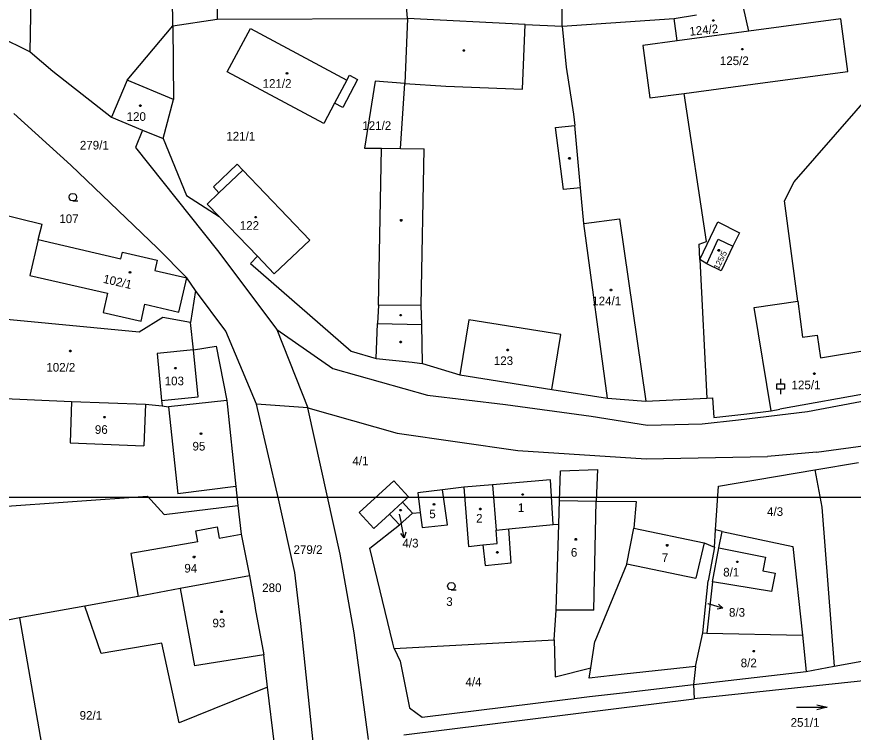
# Model space of a CAD drawing. Extents: x -812394 to -807601, y -1013097 to -1009266.
# Drawn here: x -809776.7 to -809612.2, y -1010813 to -1010672.5 of the extents above; entities that cross this region are included whole.
import ezdxf

# ---------------------------------------------------------------- set-up
doc = ezdxf.new("R2010")
doc.units = 0
for name, color, linetype in [('Default', 7, 'Continuous'), ('KN_HRANICE', 7, 'Continuous'), ('KN_KULTURY', 7, 'Continuous'), ('KN_PARCELY', 7, 'Continuous'), ('KN_SLUCKY', 7, 'Continuous'), ('LEGENDA', 7, 'Continuous')]:
    doc.layers.add(name, color=color, linetype=linetype)

# ---------------------------------------------------------------- blocks, each defined once
blk = doc.blocks.new('10292')
at = {"layer": 'Default'}
blk.add_line((0, 3), (0, 0), dxfattribs=at)
blk.add_lwpolyline([(-0.5, 2), (0, 3), (0.5, 2)], dxfattribs=at)
blk = doc.blocks.new('304')
at = {"layer": 'Default'}
blk.add_lwpolyline([(0, 0), (-0.38, 0.1), (-0.65, 0.37), (-0.75, 0.74), (-0.65, 1.11), (-0.38, 1.38), (-0.01, 1.48), (0.36, 1.38), (0.63, 1.11), (0.73, 0.73), (0.63, 0.35), (0.36, 0.08), (-0.02, -0.02), (0.98, -0.02)], dxfattribs=at)
blk = doc.blocks.new('NAHRADNI_SYMBOL')
at = {"layer": 'Default'}
blk.add_lwpolyline([(0.09, 0.15), (0.18, 0), (0.09, -0.15), (-0.09, -0.15), (-0.18, 0), (-0.09, 0.15), (0.09, 0.15)], dxfattribs=at)
blk = doc.blocks.new('802')
at = {"layer": 'Default'}
blk.add_line((-3, 0), (3, 0), dxfattribs=at)
blk.add_lwpolyline([(1, 0.5), (3, 0), (1, -0.5)], dxfattribs=at)
blk = doc.blocks.new('318')
at = {"layer": 'Default'}
blk.add_line((0, 2), (0, 3), dxfattribs=at)
blk.add_lwpolyline([(0, 0), (0, 1), (-0.75, 1), (-0.75, 2), (0, 2), (0.75, 2), (0.75, 1), (0, 1)], dxfattribs=at)
blk = doc.blocks.new('402')
at = {"layer": 'Default'}
blk.add_lwpolyline([(0.09, 0.15), (0.18, 0), (0.09, -0.15), (-0.09, -0.15), (-0.18, 0), (-0.09, 0.15), (0.09, 0.15)], dxfattribs=at)

msp = doc.modelspace()

# ---------------------------------------------------------------- linework, layer by layer
at = {"layer": 'KN_HRANICE'}
for p, q in [((-809669.42, -1010674.32), (-809670.02, -1010597.72)), ((-809738.29, -1010601.65), (-809737.29, -1010672.93)), ((-809745.99, -1010674.27), (-809746.74, -1010602.54)), ((-809699.85, -1010672.81), (-809703, -1010635.36)), ((-809774.04, -1010679.33), (-809773.49, -1010652.65)), ((-809632.78, -1010675.32), (-809633.83, -1010670.62)), ((-809737.29, -1010672.93), (-809699.85, -1010672.81)), ((-809699.85, -1010672.81), (-809700.37, -1010685.55)), ((-809676.74, -1010673.97), (-809699.85, -1010672.81)), ((-809669.42, -1010674.32), (-809647.44, -1010672.82)), ((-809647.44, -1010672.82), (-809643.04, -1010672.11)), ((-809646.86, -1010677.2), (-809647.44, -1010672.82)), ((-809614.65, -1010672.88), (-809632.78, -1010675.32)), ((-809613.27, -1010683.22), (-809614.65, -1010672.88)), ((-809784.4, -1010674.33), (-809774.04, -1010679.33)), ((-809754.98, -1010684.91), (-809745.99, -1010674.27)), ((-809745.99, -1010674.27), (-809737.29, -1010672.93)), ((-809745.99, -1010674.27), (-809745.83, -1010688.74)), ((-809676.74, -1010673.97), (-809669.42, -1010674.32)), ((-809669.42, -1010674.32), (-809668.69, -1010682.36)), ((-809735.29, -1010683.27), (-809730.75, -1010674.77)), ((-809730.75, -1010674.77), (-809711.79, -1010684.94)), ((-809632.78, -1010675.32), (-809646.86, -1010677.2)), ((-809646.86, -1010677.2), (-809653.59, -1010678.08)), ((-809774.04, -1010679.33), (-809769.56, -1010683.18)), ((-809653.59, -1010678.08), (-809652.21, -1010688.42)), ((-809668.69, -1010682.36), (-809667.2, -1010691.63)), ((-809769.56, -1010683.18), (-809758.03, -1010692.2)), ((-809716.29, -1010693.43), (-809735.29, -1010683.27)), ((-809711.79, -1010684.94), (-809711.27, -1010683.97)), ((-809711.27, -1010683.97), (-809709.68, -1010684.81)), ((-809630.51, -1010685.51), (-809613.27, -1010683.22)), ((-809754.98, -1010684.91), (-809758.03, -1010692.2)), ((-809709.68, -1010684.81), (-809712.59, -1010690.29)), ((-809706.24, -1010685.14), (-809708.32, -1010698.31)), ((-809700.37, -1010685.55), (-809706.24, -1010685.14)), ((-809701.22, -1010698.32), (-809700.37, -1010685.55)), ((-809645.48, -1010687.51), (-809630.51, -1010685.51)), ((-809652.21, -1010688.42), (-809645.48, -1010687.51)), ((-809641.11, -1010716.62), (-809645.48, -1010687.51)), ((-809747.86, -1010696.38), (-809745.83, -1010688.74)), ((-809714.18, -1010689.45), (-809716.29, -1010693.43)), ((-809712.59, -1010690.29), (-809714.18, -1010689.45)), ((-809777.22, -1010691.48), (-809766.01, -1010701.62)), ((-809758.03, -1010692.2), (-809751.95, -1010694.73)), ((-809667.2, -1010691.63), (-809666.99, -1010693.85)), ((-809665.84, -1010706.07), (-809666.99, -1010693.85)), ((-809751.95, -1010694.73), (-809753.31, -1010698.15)), ((-809751.95, -1010694.73), (-809747.86, -1010696.38)), ((-809747.86, -1010696.38), (-809743.3, -1010707.57)), ((-809753.31, -1010698.15), (-809737.22, -1010718.42)), ((-809708.32, -1010698.31), (-809704.94, -1010698.29)), ((-809705.58, -1010729.13), (-809704.94, -1010698.29)), ((-809704.94, -1010698.29), (-809701.22, -1010698.32)), ((-809766.01, -1010701.62), (-809749.02, -1010717.93)), ((-809738.02, -1010705.9), (-809733.32, -1010701.42)), ((-809733.32, -1010701.42), (-809732.21, -1010702.59)), ((-809732.21, -1010702.59), (-809719.07, -1010716.39)), ((-809739.24, -1010709.28), (-809736.91, -1010707.06)), ((-809736.91, -1010707.06), (-809738.02, -1010705.9)), ((-809665.18, -1010713.11), (-809665.84, -1010706.07)), ((-809743.3, -1010707.57), (-809736.88, -1010711.74)), ((-809736.88, -1010711.74), (-809739.24, -1010709.28)), ((-809781.21, -1010710.87), (-809771.66, -1010713.22)), ((-809729.37, -1010719.53), (-809736.88, -1010711.74)), ((-809772.47, -1010716.21), (-809771.66, -1010713.22)), ((-809660.52, -1010747.43), (-809665.18, -1010713.11)), ((-809642.41, -1010720.19), (-809638.87, -1010712.74)), ((-809638.87, -1010712.74), (-809634.6, -1010714.95)), ((-809634.6, -1010714.95), (-809635.89, -1010717.53)), ((-809772.47, -1010716.21), (-809756.21, -1010720.01)), ((-809719.07, -1010716.39), (-809726.06, -1010722.97)), ((-809642.51, -1010717.16), (-809641.11, -1010716.62)), ((-809642.41, -1010720.19), (-809642.51, -1010717.16)), ((-809756.21, -1010720.01), (-809755.91, -1010718.7)), ((-809755.91, -1010718.7), (-809749.04, -1010720.31)), ((-809749.02, -1010717.93), (-809743.23, -1010723.77)), ((-809737.22, -1010718.42), (-809725.56, -1010733.93)), ((-809635.89, -1010717.53), (-809638.17, -1010722.36)), ((-809749.04, -1010720.31), (-809749.51, -1010722.3)), ((-809729.37, -1010719.53), (-809730.7, -1010720.97)), ((-809726.06, -1010722.97), (-809729.37, -1010719.53)), ((-809642.41, -1010720.19), (-809641.01, -1010747.39)), ((-809641.03, -1010721), (-809642.41, -1010720.19)), ((-809730.7, -1010720.97), (-809710.9, -1010738.19)), ((-809638.17, -1010722.36), (-809641.03, -1010721)), ((-809749.51, -1010722.3), (-809743.23, -1010723.77)), ((-809741.5, -1010726.25), (-809743.23, -1010723.77)), ((-809741.5, -1010726.25), (-809742.53, -1010732.53)), ((-809735.54, -1010734.22), (-809741.5, -1010726.25)), ((-809623.13, -1010728.35), (-809622.2, -1010735.4)), ((-809705.58, -1010729.13), (-809705.74, -1010732.73)), ((-809752.63, -1010734.46), (-809779.32, -1010731.85)), ((-809747.95, -1010731.58), (-809752.63, -1010734.46)), ((-809742.53, -1010732.53), (-809747.95, -1010731.58)), ((-809741.93, -1010737.9), (-809742.53, -1010732.53)), ((-809706.04, -1010739.63), (-809705.74, -1010732.73)), ((-809729.55, -1010748.61), (-809735.54, -1010734.22)), ((-809725.56, -1010733.93), (-809719.43, -1010749.27)), ((-809725.56, -1010733.93), (-809714.56, -1010741.6)), ((-809741.93, -1010737.9), (-809749.09, -1010738.63)), ((-809749.09, -1010738.63), (-809748.19, -1010747.84)), ((-809741.93, -1010737.9), (-809737.44, -1010737.2)), ((-809737.44, -1010737.2), (-809735.38, -1010747.89)), ((-809710.9, -1010738.19), (-809706.04, -1010739.63)), ((-809618.66, -1010739.51), (-809608.17, -1010737.7)), ((-809706.04, -1010739.63), (-809698.97, -1010740.34)), ((-809714.56, -1010741.6), (-809695.94, -1010746.84)), ((-809698.97, -1010740.34), (-809697.48, -1010740.51)), ((-809697.48, -1010740.51), (-809696.89, -1010740.57)), ((-809696.89, -1010740.57), (-809689.54, -1010742.83)), ((-809689.54, -1010742.83), (-809671.5, -1010745.72)), ((-809695.94, -1010746.84), (-809680.59, -1010748.64)), ((-809671.5, -1010745.72), (-809660.52, -1010747.43)), ((-809606.66, -1010745.99), (-809626.64, -1010749.55)), ((-809621.25, -1010750.05), (-809601.6, -1010746.29)), ((-809785.91, -1010747.13), (-809765.89, -1010748.07)), ((-809765.89, -1010748.07), (-809766.17, -1010756.16)), ((-809765.89, -1010748.07), (-809751.37, -1010748.58)), ((-809748.19, -1010747.84), (-809748.08, -1010748.94)), ((-809735.38, -1010747.89), (-809746.82, -1010749.08)), ((-809735.38, -1010747.89), (-809733.57, -1010764.79)), ((-809660.52, -1010747.43), (-809652.99, -1010747.99)), ((-809652.99, -1010747.99), (-809641.01, -1010747.39)), ((-809641.01, -1010747.39), (-809639.91, -1010747.34)), ((-809639.91, -1010747.34), (-809639.63, -1010751.19)), ((-809751.37, -1010748.58), (-809751.66, -1010756.76)), ((-809751.37, -1010748.58), (-809748.08, -1010748.94)), ((-809748.08, -1010748.94), (-809746.82, -1010749.08)), ((-809719.43, -1010749.27), (-809729.55, -1010748.61)), ((-809725.23, -1010767.15), (-809729.55, -1010748.61)), ((-809713.08, -1010778.05), (-809719.43, -1010749.27)), ((-809719.43, -1010749.27), (-809701.9, -1010754.25)), ((-809680.59, -1010748.64), (-809663.74, -1010750.97)), ((-809634.81, -1010751.63), (-809621.25, -1010750.05)), ((-809633.16, -1010750.47), (-809628.36, -1010749.86)), ((-809628.36, -1010749.86), (-809626.64, -1010749.55)), ((-809663.74, -1010750.97), (-809652.69, -1010752.68)), ((-809641.93, -1010752.44), (-809634.81, -1010751.63)), ((-809639.63, -1010751.19), (-809633.16, -1010750.47)), ((-809652.69, -1010752.68), (-809641.93, -1010752.44)), ((-809701.9, -1010754.25), (-809678.17, -1010757.69)), ((-809766.17, -1010756.16), (-809751.66, -1010756.76)), ((-809619.48, -1010758), (-809604.22, -1010755.92)), ((-809678.17, -1010757.69), (-809652.96, -1010759.33)), ((-809619.48, -1010758), (-809629.11, -1010758.87)), ((-809652.96, -1010759.33), (-809629.11, -1010758.87)), ((-809669.98, -1010767.52), (-809669.8, -1010761.66)), ((-809669.8, -1010761.66), (-809662.52, -1010761.44)), ((-809662.52, -1010761.44), (-809662.78, -1010767.62)), ((-809638.74, -1010764.69), (-809619.76, -1010761.5)), ((-809619.76, -1010761.5), (-809611.19, -1010760.06)), ((-809619.76, -1010761.5), (-809618.42, -1010768.8)), ((-809733.57, -1010764.79), (-809733.18, -1010768.47)), ((-809702.57, -1010763.63), (-809709.33, -1010769.84)), ((-809699.69, -1010766.77), (-809702.57, -1010763.63)), ((-809688.81, -1010764.89), (-809692.96, -1010765.39)), ((-809683.14, -1010764.42), (-809688.81, -1010764.89)), ((-809688.81, -1010764.89), (-809687.88, -1010776.52)), ((-809671.72, -1010763.46), (-809683.14, -1010764.42)), ((-809683.14, -1010764.42), (-809682.45, -1010773.34)), ((-809671.19, -1010772.24), (-809671.72, -1010763.46)), ((-809639.3, -1010773.28), (-809638.74, -1010764.69)), ((-809692.96, -1010765.39), (-809697.85, -1010765.98)), ((-809697.85, -1010765.98), (-809697.36, -1010769.88)), ((-809692.01, -1010772.28), (-809692.96, -1010765.39)), ((-809794.5, -1010769.7), (-809750.96, -1010766.66)), ((-809750.96, -1010766.66), (-809747.68, -1010770.25)), ((-809722.03, -1010781.65), (-809725.23, -1010767.15)), ((-809700.87, -1010767.86), (-809699.69, -1010766.77)), ((-809698.9, -1010770), (-809700.87, -1010767.86)), ((-809670.12, -1010772.14), (-809669.98, -1010767.52)), ((-809662.78, -1010767.62), (-809654.89, -1010767.73)), ((-809654.89, -1010767.73), (-809655.37, -1010772.93)), ((-809747.68, -1010770.25), (-809733.18, -1010768.47)), ((-809733.18, -1010768.47), (-809732.57, -1010774.14)), ((-809709.33, -1010769.84), (-809706.45, -1010772.98)), ((-809698.9, -1010770), (-809697.36, -1010769.88)), ((-809697.36, -1010769.88), (-809696.98, -1010772.84)), ((-809618.42, -1010768.8), (-809615.96, -1010800.09)), ((-809706.45, -1010772.98), (-809703.38, -1010770.17)), ((-809703.38, -1010770.17), (-809701.41, -1010772.31)), ((-809701.41, -1010772.31), (-809698.9, -1010770)), ((-809707.23, -1010776.9), (-809701.41, -1010772.31)), ((-809696.98, -1010772.84), (-809692.01, -1010772.28)), ((-809682.45, -1010773.34), (-809679.95, -1010773.09)), ((-809679.95, -1010773.09), (-809671.19, -1010772.24)), ((-809679.45, -1010779.76), (-809679.95, -1010773.09)), ((-809671.19, -1010772.24), (-809670.12, -1010772.14)), ((-809670.64, -1010789.08), (-809670.12, -1010772.14)), ((-809656.71, -1010779.93), (-809655.37, -1010772.93)), ((-809655.37, -1010772.93), (-809641.57, -1010775.83)), ((-809732.57, -1010774.14), (-809730.91, -1010782.33)), ((-809639.52, -1010776.68), (-809639.3, -1010773.28)), ((-809638.02, -1010773.59), (-809639.3, -1010773.28)), ((-809638.65, -1010776.84), (-809638.02, -1010773.59)), ((-809638.02, -1010773.59), (-809624.14, -1010776.53)), ((-809687.88, -1010776.52), (-809685.04, -1010776.24)), ((-809685.04, -1010776.24), (-809684.59, -1010780.3)), ((-809641.57, -1010775.83), (-809639.52, -1010776.68)), ((-809710.32, -1010793.53), (-809713.08, -1010778.05)), ((-809702.75, -1010795.56), (-809707.23, -1010776.9)), ((-809639.52, -1010776.68), (-809640.74, -1010783.28)), ((-809639.93, -1010783.49), (-809638.65, -1010776.84)), ((-809624.14, -1010776.53), (-809622.24, -1010794)), ((-809684.59, -1010780.3), (-809679.45, -1010779.76)), ((-809656.71, -1010779.93), (-809663.05, -1010795.21)), ((-809730.91, -1010782.33), (-809744.52, -1010784.82)), ((-809730.91, -1010782.33), (-809729.89, -1010788.11)), ((-809720.85, -1010791.69), (-809722.03, -1010781.65)), ((-809641.81, -1010793.54), (-809640.74, -1010783.28)), ((-809639.93, -1010783.49), (-809640.99, -1010793.56)), ((-809752.77, -1010786.34), (-809763.26, -1010788.24)), ((-809744.52, -1010784.82), (-809752.77, -1010786.34)), ((-809763.26, -1010788.24), (-809776.12, -1010790.59)), ((-809760.07, -1010797.59), (-809763.26, -1010788.24)), ((-809729.89, -1010788.11), (-809729.78, -1010788.7)), ((-809729.78, -1010788.7), (-809728.11, -1010797.8)), ((-809671, -1010794.86), (-809670.64, -1010789.08)), ((-809776.12, -1010790.59), (-809802.82, -1010795.47)), ((-809776.12, -1010790.59), (-809768.91, -1010832.11)), ((-809718.25, -1010816.21), (-809720.85, -1010791.69)), ((-809707.49, -1010814.44), (-809710.32, -1010793.53)), ((-809643.26, -1010800.13), (-809641.81, -1010793.54)), ((-809641.81, -1010793.54), (-809640.99, -1010793.56)), ((-809640.99, -1010793.56), (-809622.24, -1010794)), ((-809622.24, -1010794), (-809621.47, -1010801.11)), ((-809748.14, -1010795.55), (-809760.07, -1010797.59)), ((-809744.75, -1010811.18), (-809748.14, -1010795.55)), ((-809702.5, -1010796.59), (-809702.75, -1010795.56)), ((-809702.5, -1010796.59), (-809671, -1010794.86)), ((-809671, -1010794.86), (-809670.86, -1010802.13)), ((-809663.83, -1010800.36), (-809663.05, -1010795.21)), ((-809615.96, -1010800.09), (-809588.54, -1010794.9)), ((-809727.35, -1010804.19), (-809728.11, -1010797.8)), ((-809702.5, -1010796.59), (-809701.33, -1010799.05)), ((-809701.33, -1010799.05), (-809699.46, -1010808.24)), ((-809670.86, -1010802.13), (-809663.83, -1010800.36)), ((-809664.14, -1010802.41), (-809663.83, -1010800.36)), ((-809643.26, -1010800.13), (-809657.25, -1010801.66)), ((-809643.26, -1010800.13), (-809643.65, -1010803.69)), ((-809643.65, -1010803.69), (-809621.47, -1010801.11)), ((-809621.47, -1010801.11), (-809615.96, -1010800.09)), ((-809657.25, -1010801.66), (-809664.14, -1010802.41)), ((-809600.38, -1010801.89), (-809643.49, -1010806.47)), ((-809727.35, -1010804.19), (-809744.75, -1010811.18)), ((-809726.02, -1010815.44), (-809727.35, -1010804.19)), ((-809657.57, -1010805.27), (-809643.65, -1010803.69)), ((-809643.65, -1010803.69), (-809643.49, -1010806.47)), ((-809696.99, -1010810.11), (-809664.09, -1010806.01)), ((-809664.09, -1010806.01), (-809657.57, -1010805.27)), ((-809700.6, -1010813.52), (-809643.49, -1010806.47)), ((-809699.46, -1010808.24), (-809696.99, -1010810.11))]:
    msp.add_line(p, q, dxfattribs=at)
for points in [[(-809623.13, -1010728.35), (-809625.78, -1010708.61), (-809623.83, -1010704.87), (-809603.55, -1010681.64)], [(-809622.2, -1010735.4), (-809619.34, -1010735.04), (-809618.66, -1010739.51)]]:
    msp.add_lwpolyline(points, dxfattribs=at)
at = {"layer": 'KN_PARCELY'}
for p, q in [((-809701.47, -1010770.18), (-809701.11, -1010771.9)), ((-809640.83, -1010787.76), (-809640.77, -1010787.78))]:
    msp.add_line(p, q, dxfattribs=at)
at = {"layer": 'KN_SLUCKY'}
for p, q in [((-809677.26, -1010686.71), (-809676.74, -1010673.97)), ((-809745.83, -1010688.74), (-809754.98, -1010684.91)), ((-809711.79, -1010684.94), (-809714.18, -1010689.45)), ((-809700.37, -1010685.55), (-809692.3, -1010686.07)), ((-809692.3, -1010686.07), (-809677.26, -1010686.71)), ((-809670.75, -1010694.2), (-809666.99, -1010693.85)), ((-809669.2, -1010706.39), (-809670.75, -1010694.2)), ((-809701.22, -1010698.32), (-809696.59, -1010698.39)), ((-809697.15, -1010729.18), (-809696.59, -1010698.39)), ((-809736.91, -1010707.06), (-809732.21, -1010702.59)), ((-809665.84, -1010706.07), (-809669.2, -1010706.39)), ((-809665.18, -1010713.11), (-809658.18, -1010712.2)), ((-809658.18, -1010712.2), (-809652.99, -1010747.99)), ((-809772.47, -1010716.21), (-809774.12, -1010723.27)), ((-809641.03, -1010721), (-809638.78, -1010716.15)), ((-809638.78, -1010716.15), (-809635.89, -1010717.53)), ((-809774.12, -1010723.27), (-809758.82, -1010726.77)), ((-809744.81, -1010730.49), (-809743.23, -1010723.77)), ((-809758.82, -1010726.77), (-809759.68, -1010730.55)), ((-809631.7, -1010729.58), (-809623.13, -1010728.35)), ((-809752.23, -1010732.25), (-809751.48, -1010728.96)), ((-809751.48, -1010728.96), (-809744.81, -1010730.49)), ((-809697.15, -1010729.18), (-809705.58, -1010729.13)), ((-809697.06, -1010732.94), (-809697.15, -1010729.18)), ((-809628.36, -1010749.86), (-809631.7, -1010729.58)), ((-809759.68, -1010730.55), (-809752.23, -1010732.25)), ((-809687.81, -1010731.99), (-809689.54, -1010742.83)), ((-809669.72, -1010734.88), (-809687.81, -1010731.99)), ((-809705.74, -1010732.73), (-809697.06, -1010732.94)), ((-809696.89, -1010740.57), (-809697.06, -1010732.94)), ((-809671.5, -1010745.72), (-809669.72, -1010734.88)), ((-809741.03, -1010747.11), (-809741.93, -1010737.9)), ((-809748.19, -1010747.84), (-809741.03, -1010747.11)), ((-809746.82, -1010749.08), (-809744.99, -1010766.19)), ((-809733.57, -1010764.79), (-809744.99, -1010766.19)), ((-809703.38, -1010770.17), (-809700.87, -1010767.86)), ((-809669.98, -1010767.52), (-809662.78, -1010767.62)), ((-809663.25, -1010789.07), (-809662.78, -1010767.62)), ((-809741.47, -1010773.44), (-809737.24, -1010772.71)), ((-809737.24, -1010772.71), (-809736.89, -1010774.91)), ((-809741.08, -1010775.63), (-809741.47, -1010773.44)), ((-809736.89, -1010774.91), (-809732.57, -1010774.14)), ((-809682.24, -1010775.95), (-809682.45, -1010773.34)), ((-809741.08, -1010775.63), (-809754.27, -1010777.89)), ((-809685.04, -1010776.24), (-809682.24, -1010775.95)), ((-809641.57, -1010775.83), (-809643.15, -1010782.76)), ((-809754.27, -1010777.89), (-809752.77, -1010786.34)), ((-809638.65, -1010776.84), (-809629.49, -1010778.64)), ((-809629.49, -1010778.64), (-809630.01, -1010781.3)), ((-809656.71, -1010779.93), (-809643.15, -1010782.76)), ((-809630.01, -1010781.3), (-809627.59, -1010781.78)), ((-809627.59, -1010781.78), (-809628.3, -1010785.39)), ((-809628.3, -1010785.39), (-809639.93, -1010783.49)), ((-809744.52, -1010784.82), (-809741.75, -1010799.98)), ((-809663.25, -1010789.07), (-809670.64, -1010789.08)), ((-809728.11, -1010797.8), (-809741.75, -1010799.98))]:
    msp.add_line(p, q, dxfattribs=at)
at = {"layer": 'LEGENDA'}
msp.add_lwpolyline([(-810040.19, -1011186.89), (-809446.19, -1011186.89), (-809446.19, -1010766.89), (-810040.19, -1010766.89)], close=True, dxfattribs=at)

# ---------------------------------------------------------------- block references
at = {"layer": 'KN_KULTURY'}
for name, p in [('NAHRADNI_SYMBOL', (-809639.73, -1010673.21)), ('402', (-809688.79, -1010679.1)), ('402', (-809634.03, -1010678.83)), ('402', (-809723.54, -1010683.59)), ('402', (-809752.37, -1010689.95)), ('402', (-809668.02, -1010700.27)), ('304', (-809765.64, -1010708.64)), ('402', (-809729.71, -1010711.84)), ('402', (-809701.1, -1010712.47)), ('402', (-809638.67, -1010718.34)), ('402', (-809754.39, -1010722.67)), ('402', (-809659.85, -1010726.15)), ('402', (-809701.21, -1010731.09)), ('402', (-809701.21, -1010736.38)), ('NAHRADNI_SYMBOL', (-809766.14, -1010738.14)), ('402', (-809680.15, -1010737.92)), ('402', (-809745.47, -1010741.52)), ('318', (-809626.49, -1010746.61)), ('402', (-809619.88, -1010742.57)), ('402', (-809759.42, -1010751.14)), ('402', (-809740.45, -1010754.37)), ('402', (-809677.22, -1010766.34)), ('402', (-809694.64, -1010768.27)), ('402', (-809701.22, -1010769.4)), ('402', (-809685.53, -1010769.19)), ('402', (-809666.77, -1010775.13)), ('402', (-809648.81, -1010776.33)), ('402', (-809682.2, -1010777.69)), ('402', (-809741.8, -1010778.62)), ('402', (-809635.03, -1010779.55)), ('304', (-809691.24, -1010785.07)), ('402', (-809736.42, -1010789.35)), ('NAHRADNI_SYMBOL', (-809631.79, -1010797.12)), ('802', (-809620.36, -1010808.13))]:
    msp.add_blockref(name, p, dxfattribs=at)
at = {"layer": 'KN_PARCELY'}
for p, rotation in [((-809701.11, -1010771.9), -168.231026), ((-809640.77, -1010787.78), -106.69535899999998)]:
    msp.add_blockref('10292', p, dxfattribs=dict(at, rotation=rotation))

# ---------------------------------------------------------------- texts
for s, height, rotation, p in [('124/2', 1.7, 5.959, (-809644.36, -1010676.21)), ('125/5', 1.14, 63.426, (-809638.7, -1010722.21)), ('102/1', 1.7, 347.27, (-809759.8, -1010724.72))]:
    msp.add_text(s, height=height, rotation=rotation, dxfattribs=at).set_placement(p)
for s, height, p in [('125/2', 1.7, (-809638.46, -1010681.96)), ('121/2', 1.7, (-809728.34, -1010686.42)), ('120', 1.7, (-809755.07, -1010692.92)), ('121/2', 1.7, (-809708.74, -1010694.7)), ('121/1', 1.7, (-809735.47, -1010696.78)), ('279/1', 1.7, (-809764.26, -1010698.55)), ('107', 1.7, (-809768.3, -1010713)), ('122', 1.7, (-809732.83, -1010714.32)), ('124/1', 1.7, (-809663.55, -1010729.15)), ('123', 1.7, (-809682.89, -1010740.89)), ('102/2', 1.7, (-809770.85, -1010742.19)), ('103', 1.7, (-809747.59, -1010744.87)), ('125/1', 1.7, (-809624.37, -1010745.65)), ('96', 1.7, (-809761.31, -1010754.42)), ('95', 1.7, (-809742.12, -1010757.69)), ('4/1', 1.7, (-809710.68, -1010760.57)), ('1', 1.7, (-809678.15, -1010769.76)), ('5', 1.7, (-809695.57, -1010770.99)), ('4/3', 1.7, (-809629.18, -1010770.54)), ('4/3', 0.1, (-809701.62, -1010770.18)), ('2', 1.7, (-809686.37, -1010771.85)), ('279/2', 1.7, (-809722.26, -1010778.01)), ('4/3', 1.7, (-809700.85, -1010776.74)), ('6', 1.7, (-809667.74, -1010778.55)), ('7', 1.7, (-809649.85, -1010779.58)), ('94', 1.7, (-809743.72, -1010781.67)), ('8/1', 1.7, (-809637.8, -1010782.44)), ('280', 1.7, (-809728.42, -1010785.5)), ('3', 1.7, (-809692.24, -1010788.22)), ('8/3', 0.1, (-809640.98, -1010787.76)), ('8/3', 1.7, (-809636.66, -1010790.34)), ('93', 1.7, (-809738.2, -1010792.43)), ('8/2', 1.7, (-809634.36, -1010800.27)), ('4/4', 1.7, (-809688.46, -1010804.01)), ('92/1', 1.7, (-809764.31, -1010810.58)), ('251/1', 1.7, (-809624.55, -1010811.97))]:
    msp.add_text(s, height=height, dxfattribs=at).set_placement(p)

doc.saveas('drawing.dxf')
